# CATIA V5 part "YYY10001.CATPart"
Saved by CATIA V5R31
Part number: YYY10001
Source: Unknown
Bounding box of the stored display mesh (mm): x -717.032 to -580.495, y -63.475 to -63.475, z -63.296 to 60.05
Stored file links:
  \\cad-nas02\CATIA1212\BODY_DEPARTMENT8\JAMA\変換データ\STEP3_最終_20240115\01_いすゞ板金\new_ファイル名修正後\CATIA_V5_20240122\YYY10001.CATPart
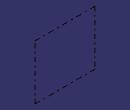
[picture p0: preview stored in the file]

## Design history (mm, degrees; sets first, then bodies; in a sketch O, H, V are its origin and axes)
Set1
  Line1 "LINE #2547": stored without definition
  Line2 "LINE #2548": stored without definition
  Line3 "LINE #2549": stored without definition
  Line4 "LINE #2550": stored without definition
  Line5 "LINE #2551": stored without definition
  Line6 "LINE #2552": stored without definition
  DatumCurve1 "ELLIPSE #2537"
  DatumCurve2 "ELLIPSE #2538"
  Plane1: type 3Points, Element1 vertex of Line2, Element2 vertex of Line1, Element3 vertex of Line1
  Sketch1 on Plane1, origin (0, -63.4746, 0), H (1, 0, 0), V (0, 0, 1)
    line L1 (-717.0573, 60.0872) -> (-580.5445, 60.0872)
    line L2 (-580.5445, 60.0872) -> (-580.5445, -63.2383)
    line L3 (-580.5445, -63.2383) -> (-717.0573, -63.2383)
    line L4 (-717.0573, -63.2383) -> (-717.0573, 60.0872)
    horizontal: L1 H, L3 H
    vertical: L2 V, L4 V
  Fill1: Boundary Sketch1
  Sketch2 on Plane1, origin (0, -63.4746, 0), H (1, 0, 0), V (0, 0, 1)
    line L1 (-717.0321, 60.0497) -> (-580.4949, 60.0497)
    line L2 (-580.4949, 60.0497) -> (-580.4949, -63.2962)
    line L3 (-580.4949, -63.2962) -> (-717.0321, -63.2962)
    line L4 (-717.0321, -63.2962) -> (-717.0321, 60.0497)
    horizontal: L1 H, L3 H
    vertical: L2 V, L4 V
  Fill2: Boundary Sketch2
Body1 (main body)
